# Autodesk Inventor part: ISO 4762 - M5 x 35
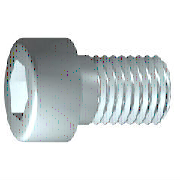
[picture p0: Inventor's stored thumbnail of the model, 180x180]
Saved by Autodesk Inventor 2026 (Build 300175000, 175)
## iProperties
IsCustomPart: 1
Created: 2022-02
Part Number: ISO 4762 - M5 x 35
Material: Steel, Mild
Description: Hexagon Socket Head Cap Screw
Document SubType Name: Modeling
Standard: ISO 4762
Designer: Lars Bertram Pedersen
Standard Revision: Fourth edition 2004-03-01
Standards Organization: ISO
Language: en-US
Size Designation: M5 x 35
Categories: <MemberInstance><Categories><Category DisplayName="Fasteners" InternalName="e4da775c-781d-43d5-af7c-5136215cf5a6" Mnemonic="FSTN"><Category DisplayName="Bolts"
Density: 7.85 g/cm^3
Appearance: Silver
Mass: 7.2686 g
Surface Area: 8.23857 cm^2
Volume: 0.925936 cm^3
Stock Number: Lager
Author: Lars Bertram Pedersen
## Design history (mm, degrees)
workplane "Work Plane1"
fillet "Fillet2" dims "d30" = 0.1 (= R)
revolve "Body" stored, may be unused: angle "d10" = 90 deg
sketch "Sketch2"
  geometry: L1 (0, -5.95)-(0, 5.95) reference; L2 (-5.95, 0)-(5.95, 0) reference; L3 (2.309, 0)-(1.155, -2); L4 (1.155, -2)-(-1.155, -2); L5 (-1.155, -2)-(-2.309, 0); L6 (-2.309, 0)-(-1.155, 2); L7 (-1.155, 2)-(1.155, 2); L8 (1.155, 2)-(2.309, 0); 2 further points
  constraints: 12 end point, 1 coincident, 1 horizontal alignment, 1 point on line, 12 other
extrude "Slot" join sketch "Sketch2" stored distance "d11" = 10; taper "d12" = 0 deg
body "Solid1"
fillet "Fillet1" dims "d17" = 0.5 (= RR)
feature "Thread" dims "d13" = 22 (= GEL), "d14" = 0
chamfer "Chamfer1" distance "d15" = 0.49076 (= -0.5 x SPD + 0.5 x GD); stored, may be unused: second distance "d16" = 0.49076 (= GUL), angle "d27" = 45 deg
sketch "Sketch1"
  geometry: L1 (-1.167, 0)-(35, 0); L2 (35, 0)-(35, 2.5); L3 (35, 2.5)-(13, 2.5); L4 (13, 2.5)-(12.509, 2.5); L5 (12.509, 2.5)-(0, 2.5); L6 (0, 2.5)-(0, 4.25); L7 (0, 4.25)-(-5, 4.25); L8 (-5, 4.25)-(-5, 2.309); L9 (-5, 2.309)-(-2.5, 2.309); L10 (-2.5, 2.309)-(-1.167, 0); L11 (-13, 0)-(43, 0) reference; L12 (0, -0.85)-(0, 5.1) reference; L13 (13, 2.5)-(0, 2.5)
  constraints: 22 end point, 6 parallel, 2 collinear, 2 perpendicular, 1 horizontal, 1 point on line
  dimensions: "d1" = 22 distance from line of L3.end L2 (= GEL); "d2" = 0.49086 distance of L4.end L3.end (computed from GAL); "d3" = 5 distance between parallel lines of L8 L6 (= KOH); "d4" = 2.5 distance of L8.end L9.end (= INTI); "d5" = 60 deg angle of L10 L1; "d6" = 5 diameter of L3 L1 (= GD); "d7" = 5 diameter of L5 L1 (= BDM); "d8" = 4.6188 diameter of L9 L1 (= 1.1547 x SW); "d9" = 8.5 diameter of L7 L1 (= KOD); "d26" = 35 distance between parallel lines of L12 L2 (= NLG)
other parameters: "GD" = 5 [user parameter; used in 2 equation terms], "NLG" = 35 [user parameter; used in 1 equation term], "GEL" = 22 [user parameter; used in 2 equation terms], "KOD" = 8.5 [user parameter; used in 1 equation term], "KOH" = 5 [user parameter; used in 1 equation term], "INTI" = 2.5 [user parameter; used in 1 equation term], "GAL" = 0.49076 (= 0.61345 x PTC) [user parameter; used in 1 equation term], "GUL" = 0.49076 (= 0.61345 x PTC) [user parameter; used in 1 equation term], "BDM" = 5 (= NND) [user parameter; used in 1 equation term], "SW" = 4 [user parameter; used in 2 equation terms], "RR" = 0.5 [user parameter; used in 1 equation term], "SPD" = 4.01848 (= NND - 1.2269 x PTC) [user parameter; used in 1 equation term], "d19" = 0, "d28" = 0, "d29" = 0, "R" = 0.1 [user parameter; used in 1 equation term], "TOA" = 30 deg [user parameter], "GD1" = 4.01848 (= THREADDIA - 1.2269 x PTC) [user parameter], "THREADDIA" = 5 [user parameter; used in 1 equation term], "FAWI" = 45 deg [user parameter], "TPU" = 12.5 (computed from PTC) [user parameter], "PTC" = 0.8 [user parameter; used in 5 equation terms], "NND" = 5 [user parameter; used in 2 equation terms], "E0" = 4.62 (= 1.155 x SW) [user parameter]
